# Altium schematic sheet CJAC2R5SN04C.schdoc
size 127 x 101 mm
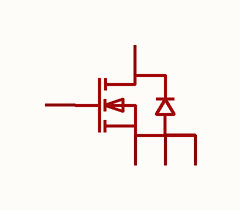
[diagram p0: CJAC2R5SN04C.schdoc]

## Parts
Q?  cjac2r5sn04c  [DFN-5_L4.9-W5.9-P1.27-LS6.2-BL]  (value not drawn)

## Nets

Not connected (* = marked no-connect by the designer): Q? 1(S) 2(S) 3(S) 4(G) 5(D)

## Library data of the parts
Q? = cjac2r5sn04c: 数量:1个N沟道;漏源电压(Vdss):40V;连续漏极电流(Id):130A;导通电阻(RDS(on)):-;耗散功率(Pd):96W;阈值电压(Vgs(th)):2.5V;; Manufacturer: CJ(江苏长电/长晶); AddInBom: yes; ModelId: d514c3869eaa4c8b9019a6aaf9755d85; ModelName: DFN-5_L4.9-W5.9-H1.0-P1.27-LS6.2-BL; ModelTransform: 202.7555,243.897,0,0,0,0,0,42.874,0; Number: 1个N沟道; Drain to Source Voltage: 40V; Current - Continuous Drain(Id): 130A; Pd - Power Dissipation: 96W; Gate Threshold Voltage (Vgs(th)): 2.5V; Gate Charge(Qg): 26.2nC@10V; Input Capacitance(Ciss): 1.743nF; Type: N沟道; Output Capacitance(Coss): 589pF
